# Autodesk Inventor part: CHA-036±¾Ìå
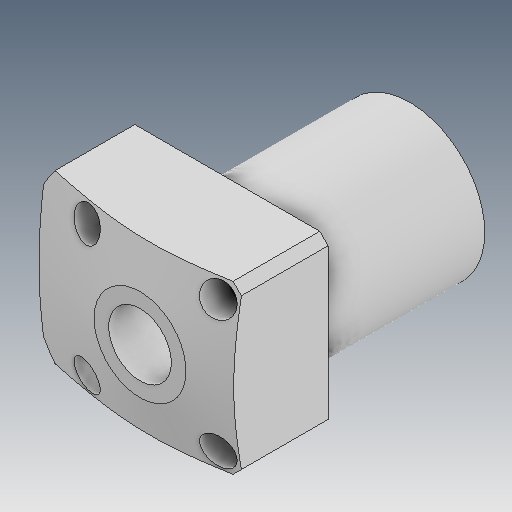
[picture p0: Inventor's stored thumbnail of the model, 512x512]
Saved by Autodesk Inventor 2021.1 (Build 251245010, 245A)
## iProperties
Created: 2019-12
Part Number: CHA-036±¾Ìå
Material: Ogólny
Document SubType Name: Modeling
Designer: user
Density: 1 g/cm^3
Appearance: Domyślna
Author: user
Revision Number: ÈÎºÎ
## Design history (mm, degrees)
feature "NONE"
node "Bryła1"
